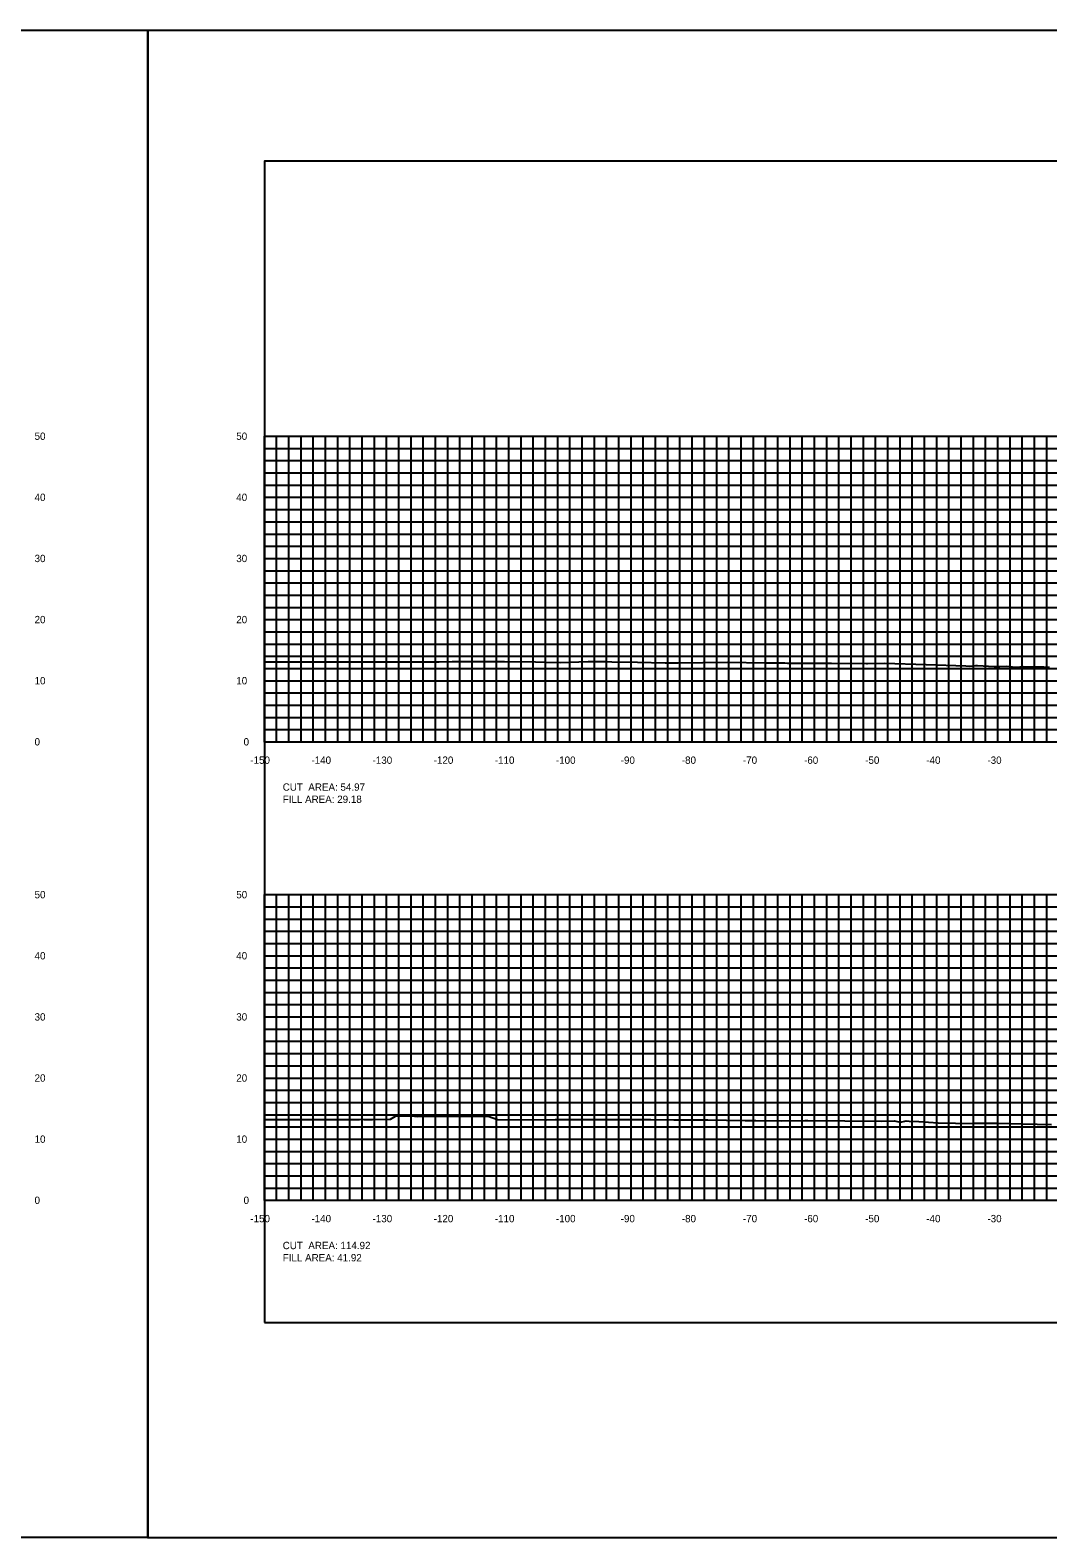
# Model space of a CAD drawing. Extents: x 1797518 to 1804843, y 248068 to 251132.
# Drawn here: x 1804482.7 to 1804649.2, y 250044.2 to 250290.9 of the extents above; entities that cross this region are included whole.
import ezdxf

# ---------------------------------------------------------------- set-up
doc = ezdxf.new("R2010")
doc.units = 0
for name, color, linetype in [('1', 7, 'Continuous'), ('10', 7, 'Continuous'), ('31', 7, 'Continuous'), ('60', 7, 'Continuous'), ('ANNO-TXT', 7, 'Continuous'), ('Level 62', 7, 'Continuous'), ('M-ROADS', 7, 'Continuous')]:
    doc.layers.add(name, color=color, linetype=linetype)

msp = doc.modelspace()

# ---------------------------------------------------------------- linework, layer by layer
msp.add_lwpolyline([(1804521, 250079.43), (1804821, 250079.43), (1804821, 250269.43), (1804521, 250269.43)], close=True)
at = {"layer": '1'}
for points in [[(1804164.33, 250290.86), (1804501.93, 250290.86), (1804501.93, 250044.24), (1804164.33, 250044.24)], [(1804501.93, 250290.86), (1804843.47, 250290.86), (1804843.47, 250044.2), (1804501.93, 250044.2)]]:
    msp.add_lwpolyline(points, close=True, dxfattribs=at)
at = {"layer": '60'}
for p, q in [((1804520.94, 250224.43), (1804521, 250224.43)), ((1804521, 250174.43), (1804521, 250224.43)), ((1804520.94, 250214.43), (1804521, 250214.43)), ((1804520.94, 250204.43), (1804521, 250204.43)), ((1804520.94, 250194.43), (1804521, 250194.43)), ((1804520.94, 250184.43), (1804521, 250184.43)), ((1804520.94, 250174.43), (1804521, 250174.43)), ((1804521, 250174.43), (1804821, 250174.43)), ((1804521, 250174.37), (1804521, 250174.43)), ((1804531, 250174.37), (1804531, 250174.43)), ((1804541, 250174.37), (1804541, 250174.43)), ((1804551, 250174.37), (1804551, 250174.43)), ((1804561, 250174.37), (1804561, 250174.43)), ((1804571, 250174.37), (1804571, 250174.43)), ((1804581, 250174.37), (1804581, 250174.43)), ((1804591, 250174.37), (1804591, 250174.43)), ((1804601, 250174.37), (1804601, 250174.43)), ((1804611, 250174.37), (1804611, 250174.43)), ((1804621, 250174.37), (1804621, 250174.43)), ((1804631, 250174.37), (1804631, 250174.43)), ((1804641, 250174.37), (1804641, 250174.43)), ((1804520.94, 250149.43), (1804521, 250149.43)), ((1804521, 250099.43), (1804521, 250149.43)), ((1804520.94, 250139.43), (1804521, 250139.43)), ((1804520.94, 250129.43), (1804521, 250129.43)), ((1804520.94, 250119.43), (1804521, 250119.43)), ((1804520.94, 250109.43), (1804521, 250109.43)), ((1804520.94, 250099.43), (1804521, 250099.43)), ((1804521, 250099.43), (1804821, 250099.43)), ((1804521, 250099.37), (1804521, 250099.43)), ((1804531, 250099.37), (1804531, 250099.43)), ((1804541, 250099.37), (1804541, 250099.43)), ((1804551, 250099.37), (1804551, 250099.43)), ((1804561, 250099.37), (1804561, 250099.43)), ((1804571, 250099.37), (1804571, 250099.43)), ((1804581, 250099.37), (1804581, 250099.43)), ((1804591, 250099.37), (1804591, 250099.43)), ((1804601, 250099.37), (1804601, 250099.43)), ((1804611, 250099.37), (1804611, 250099.43)), ((1804621, 250099.37), (1804621, 250099.43)), ((1804631, 250099.37), (1804631, 250099.43)), ((1804641, 250099.37), (1804641, 250099.43))]:
    msp.add_line(p, q, dxfattribs=at)
at = {"layer": 'Level 62'}
for p, q in [((1804521, 250224.43), (1804821, 250224.43)), ((1804521, 250174.43), (1804521, 250224.43)), ((1804523, 250174.43), (1804523, 250224.43)), ((1804525, 250174.43), (1804525, 250224.43)), ((1804527, 250174.43), (1804527, 250224.43)), ((1804529, 250174.43), (1804529, 250224.43)), ((1804531, 250174.43), (1804531, 250224.43)), ((1804533, 250174.43), (1804533, 250224.43)), ((1804535, 250174.43), (1804535, 250224.43)), ((1804537, 250174.43), (1804537, 250224.43)), ((1804539, 250174.43), (1804539, 250224.43)), ((1804541, 250174.43), (1804541, 250224.43)), ((1804543, 250174.43), (1804543, 250224.43)), ((1804545, 250174.43), (1804545, 250224.43)), ((1804547, 250174.43), (1804547, 250224.43)), ((1804549, 250174.43), (1804549, 250224.43)), ((1804551, 250174.43), (1804551, 250224.43)), ((1804553, 250174.43), (1804553, 250224.43)), ((1804555, 250174.43), (1804555, 250224.43)), ((1804557, 250174.43), (1804557, 250224.43)), ((1804559, 250174.43), (1804559, 250224.43)), ((1804561, 250174.43), (1804561, 250224.43)), ((1804563, 250174.43), (1804563, 250224.43)), ((1804565, 250174.43), (1804565, 250224.43)), ((1804567, 250174.43), (1804567, 250224.43)), ((1804569, 250174.43), (1804569, 250224.43)), ((1804571, 250174.43), (1804571, 250224.43)), ((1804573, 250174.43), (1804573, 250224.43)), ((1804575, 250174.43), (1804575, 250224.43)), ((1804577, 250174.43), (1804577, 250224.43)), ((1804579, 250174.43), (1804579, 250224.43)), ((1804581, 250174.43), (1804581, 250224.43)), ((1804583, 250174.43), (1804583, 250224.43)), ((1804585, 250174.43), (1804585, 250224.43)), ((1804587, 250174.43), (1804587, 250224.43)), ((1804589, 250174.43), (1804589, 250224.43)), ((1804591, 250174.43), (1804591, 250224.43)), ((1804593, 250174.43), (1804593, 250224.43)), ((1804595, 250174.43), (1804595, 250224.43)), ((1804597, 250174.43), (1804597, 250224.43)), ((1804599, 250174.43), (1804599, 250224.43)), ((1804601, 250174.43), (1804601, 250224.43)), ((1804603, 250174.43), (1804603, 250224.43)), ((1804605, 250174.43), (1804605, 250224.43)), ((1804607, 250174.43), (1804607, 250224.43)), ((1804609, 250174.43), (1804609, 250224.43)), ((1804611, 250174.43), (1804611, 250224.43)), ((1804613, 250174.43), (1804613, 250224.43)), ((1804615, 250174.43), (1804615, 250224.43)), ((1804617, 250174.43), (1804617, 250224.43)), ((1804619, 250174.43), (1804619, 250224.43)), ((1804621, 250174.43), (1804621, 250224.43)), ((1804623, 250174.43), (1804623, 250224.43)), ((1804625, 250174.43), (1804625, 250224.43)), ((1804627, 250174.43), (1804627, 250224.43)), ((1804629, 250174.43), (1804629, 250224.43)), ((1804631, 250174.43), (1804631, 250224.43)), ((1804633, 250174.43), (1804633, 250224.43)), ((1804635, 250174.43), (1804635, 250224.43)), ((1804637, 250174.43), (1804637, 250224.43)), ((1804639, 250174.43), (1804639, 250224.43)), ((1804641, 250174.43), (1804641, 250224.43)), ((1804643, 250174.43), (1804643, 250224.43)), ((1804645, 250174.43), (1804645, 250224.43)), ((1804647, 250174.43), (1804647, 250224.43)), ((1804649, 250174.43), (1804649, 250224.43)), ((1804521, 250222.43), (1804821, 250222.43)), ((1804521, 250220.43), (1804821, 250220.43)), ((1804521, 250218.43), (1804821, 250218.43)), ((1804521, 250216.43), (1804821, 250216.43)), ((1804521, 250214.43), (1804821, 250214.43)), ((1804521, 250212.43), (1804821, 250212.43)), ((1804521, 250210.43), (1804821, 250210.43)), ((1804521, 250208.43), (1804821, 250208.43)), ((1804521, 250206.43), (1804821, 250206.43)), ((1804521, 250204.43), (1804821, 250204.43)), ((1804521, 250202.43), (1804821, 250202.43)), ((1804521, 250200.43), (1804821, 250200.43)), ((1804521, 250198.43), (1804821, 250198.43)), ((1804521, 250196.43), (1804821, 250196.43)), ((1804521, 250194.43), (1804821, 250194.43)), ((1804521, 250192.43), (1804821, 250192.43)), ((1804521, 250190.43), (1804821, 250190.43)), ((1804521, 250188.43), (1804821, 250188.43)), ((1804521, 250186.43), (1804821, 250186.43)), ((1804521, 250184.43), (1804821, 250184.43)), ((1804521, 250182.43), (1804821, 250182.43)), ((1804521, 250180.43), (1804821, 250180.43)), ((1804521, 250178.43), (1804821, 250178.43)), ((1804521, 250176.43), (1804821, 250176.43)), ((1804521, 250174.43), (1804821, 250174.43)), ((1804521, 250149.43), (1804821, 250149.43)), ((1804521, 250099.43), (1804521, 250149.43)), ((1804523, 250099.43), (1804523, 250149.43)), ((1804525, 250099.43), (1804525, 250149.43)), ((1804527, 250099.43), (1804527, 250149.43)), ((1804529, 250099.43), (1804529, 250149.43)), ((1804531, 250099.43), (1804531, 250149.43)), ((1804533, 250099.43), (1804533, 250149.43)), ((1804535, 250099.43), (1804535, 250149.43)), ((1804537, 250099.43), (1804537, 250149.43)), ((1804539, 250099.43), (1804539, 250149.43)), ((1804541, 250099.43), (1804541, 250149.43)), ((1804543, 250099.43), (1804543, 250149.43)), ((1804545, 250099.43), (1804545, 250149.43)), ((1804547, 250099.43), (1804547, 250149.43)), ((1804549, 250099.43), (1804549, 250149.43)), ((1804551, 250099.43), (1804551, 250149.43)), ((1804553, 250099.43), (1804553, 250149.43)), ((1804555, 250099.43), (1804555, 250149.43)), ((1804557, 250099.43), (1804557, 250149.43)), ((1804559, 250099.43), (1804559, 250149.43)), ((1804561, 250099.43), (1804561, 250149.43)), ((1804563, 250099.43), (1804563, 250149.43)), ((1804565, 250099.43), (1804565, 250149.43)), ((1804567, 250099.43), (1804567, 250149.43)), ((1804569, 250099.43), (1804569, 250149.43)), ((1804571, 250099.43), (1804571, 250149.43)), ((1804573, 250099.43), (1804573, 250149.43)), ((1804575, 250099.43), (1804575, 250149.43)), ((1804577, 250099.43), (1804577, 250149.43)), ((1804579, 250099.43), (1804579, 250149.43)), ((1804581, 250099.43), (1804581, 250149.43)), ((1804583, 250099.43), (1804583, 250149.43)), ((1804585, 250099.43), (1804585, 250149.43)), ((1804587, 250099.43), (1804587, 250149.43)), ((1804589, 250099.43), (1804589, 250149.43)), ((1804591, 250099.43), (1804591, 250149.43)), ((1804593, 250099.43), (1804593, 250149.43)), ((1804595, 250099.43), (1804595, 250149.43)), ((1804597, 250099.43), (1804597, 250149.43)), ((1804599, 250099.43), (1804599, 250149.43)), ((1804601, 250099.43), (1804601, 250149.43)), ((1804603, 250099.43), (1804603, 250149.43)), ((1804605, 250099.43), (1804605, 250149.43)), ((1804607, 250099.43), (1804607, 250149.43)), ((1804609, 250099.43), (1804609, 250149.43)), ((1804611, 250099.43), (1804611, 250149.43)), ((1804613, 250099.43), (1804613, 250149.43)), ((1804615, 250099.43), (1804615, 250149.43)), ((1804617, 250099.43), (1804617, 250149.43)), ((1804619, 250099.43), (1804619, 250149.43)), ((1804621, 250099.43), (1804621, 250149.43)), ((1804623, 250099.43), (1804623, 250149.43)), ((1804625, 250099.43), (1804625, 250149.43)), ((1804627, 250099.43), (1804627, 250149.43)), ((1804629, 250099.43), (1804629, 250149.43)), ((1804631, 250099.43), (1804631, 250149.43)), ((1804633, 250099.43), (1804633, 250149.43)), ((1804635, 250099.43), (1804635, 250149.43)), ((1804637, 250099.43), (1804637, 250149.43)), ((1804639, 250099.43), (1804639, 250149.43)), ((1804641, 250099.43), (1804641, 250149.43)), ((1804643, 250099.43), (1804643, 250149.43)), ((1804645, 250099.43), (1804645, 250149.43)), ((1804647, 250099.43), (1804647, 250149.43)), ((1804649, 250099.43), (1804649, 250149.43)), ((1804521, 250147.43), (1804821, 250147.43)), ((1804521, 250145.43), (1804821, 250145.43)), ((1804521, 250143.43), (1804821, 250143.43)), ((1804521, 250141.43), (1804821, 250141.43)), ((1804521, 250139.43), (1804821, 250139.43)), ((1804521, 250137.43), (1804821, 250137.43)), ((1804521, 250135.43), (1804821, 250135.43)), ((1804521, 250133.43), (1804821, 250133.43)), ((1804521, 250131.43), (1804821, 250131.43)), ((1804521, 250129.43), (1804821, 250129.43)), ((1804521, 250127.43), (1804821, 250127.43)), ((1804521, 250125.43), (1804821, 250125.43)), ((1804521, 250123.43), (1804821, 250123.43)), ((1804521, 250121.43), (1804821, 250121.43)), ((1804521, 250119.43), (1804821, 250119.43)), ((1804521, 250117.43), (1804821, 250117.43)), ((1804521, 250115.43), (1804821, 250115.43)), ((1804521, 250113.43), (1804821, 250113.43)), ((1804521, 250111.43), (1804821, 250111.43)), ((1804521, 250109.43), (1804821, 250109.43)), ((1804521, 250107.43), (1804821, 250107.43)), ((1804521, 250105.43), (1804821, 250105.43)), ((1804521, 250103.43), (1804821, 250103.43)), ((1804521, 250101.43), (1804821, 250101.43)), ((1804521, 250099.43), (1804821, 250099.43))]:
    msp.add_line(p, q, dxfattribs=at)
at = {"layer": 'M-ROADS'}
for points in [[(1804521, 250187.52), (1804521.07, 250187.52), (1804525.7, 250187.52), (1804527.33, 250187.5), (1804529.39, 250187.51), (1804530.58, 250187.5), (1804530.98, 250187.53), (1804531.26, 250187.51), (1804532.33, 250187.53), (1804532.71, 250187.53), (1804533.65, 250187.54), (1804537.68, 250187.53), (1804540.91, 250187.54), (1804540.97, 250187.54), (1804541.01, 250187.54), (1804549.58, 250187.51), (1804551.71, 250187.55), (1804553.12, 250187.56), (1804555.8, 250187.57), (1804557.08, 250187.58), (1804559.23, 250187.59), (1804559.37, 250187.58), (1804559.7, 250187.59), (1804559.83, 250187.59), (1804560.3, 250187.58), (1804565.38, 250187.51), (1804566.9, 250187.48), (1804569.43, 250187.39), (1804569.47, 250187.39), (1804573.95, 250187.57), (1804576.78, 250187.56), (1804578.96, 250187.48), (1804581.06, 250187.49), (1804582.07, 250187.47), (1804586.59, 250187.38), (1804588.68, 250187.33), (1804596.78, 250187.45), (1804602.93, 250187.34), (1804605.74, 250187.34), (1804606.14, 250187.33), (1804606.58, 250187.31), (1804609.81, 250187.31), (1804613.81, 250187.29), (1804619.53, 250187.26), (1804619.6, 250187.26), (1804619.66, 250187.26), (1804622.46, 250187.3), (1804629.28, 250187.07), (1804635.74, 250186.85), (1804636.29, 250186.83), (1804637.37, 250186.93), (1804637.53, 250186.9), (1804637.67, 250186.94), (1804640.4, 250186.78), (1804640.72, 250186.74), (1804641.34, 250186.74), (1804642.35, 250186.79), (1804643.92, 250186.63), (1804643.93, 250186.63), (1804645.2, 250186.78), (1804648.52, 250186.71), (1804649.46, 250186.62)], [(1804521, 250112.65), (1804528.19, 250112.64), (1804531.51, 250112.66), (1804534.47, 250112.66), (1804535.76, 250112.65), (1804536.58, 250112.63), (1804537.05, 250112.67), (1804537.26, 250112.65), (1804538.69, 250112.66), (1804541.64, 250112.67), (1804542.48, 250113.17), (1804544.99, 250113.24), (1804546.07, 250113.15), (1804556.04, 250113.19), (1804557.62, 250113.16), (1804559.12, 250112.62), (1804567.2, 250112.6), (1804568.58, 250112.62), (1804569.49, 250112.63), (1804571.23, 250112.64), (1804572.05, 250112.64), (1804573.65, 250112.65), (1804575.19, 250112.65), (1804576.21, 250112.66), (1804578.28, 250112.66), (1804580.09, 250112.65), (1804581.05, 250112.65), (1804581.59, 250112.64), (1804584.25, 250112.63), (1804588.01, 250112.61), (1804591.32, 250112.58), (1804592.3, 250112.57), (1804593.05, 250112.57), (1804593.55, 250112.57), (1804599.65, 250112.5), (1804601.43, 250112.47), (1804605.57, 250112.42), (1804609.45, 250112.48), (1804609.85, 250112.47), (1804609.9, 250112.47), (1804622, 250112.39), (1804624.04, 250112.4), (1804625.09, 250112.19), (1804625.98, 250112.4), (1804626.47, 250112.39), (1804628.06, 250112.29), (1804631.26, 250112.08), (1804636.92, 250112), (1804637.16, 250112.03), (1804638.44, 250112.03), (1804640.14, 250112.03), (1804641.13, 250112.02), (1804645.07, 250111.93), (1804649.78, 250111.81)]]:
    msp.add_lwpolyline(points, dxfattribs=at)

# ---------------------------------------------------------------- texts
at = {"layer": '10'}
for s, p in [('-150', (1804518.7, 250170.83)), ('-140', (1804528.7, 250170.83)), ('-130', (1804538.7, 250170.83)), ('-120', (1804548.7, 250170.83)), ('-110', (1804558.7, 250170.83)), ('-100', (1804568.7, 250170.83)), ('-90', (1804579.3, 250170.83)), ('-80', (1804589.3, 250170.83)), ('-70', (1804599.3, 250170.83)), ('-60', (1804609.3, 250170.83)), ('-50', (1804619.3, 250170.83)), ('-40', (1804629.3, 250170.83)), ('-30', (1804639.3, 250170.83)), ('-150', (1804518.7, 250095.83)), ('-140', (1804528.7, 250095.83)), ('-130', (1804538.7, 250095.83)), ('-120', (1804548.7, 250095.83)), ('-110', (1804558.7, 250095.83)), ('-100', (1804568.7, 250095.83)), ('-90', (1804579.3, 250095.83)), ('-80', (1804589.3, 250095.83)), ('-70', (1804599.3, 250095.83)), ('-60', (1804609.3, 250095.83)), ('-50', (1804619.3, 250095.83)), ('-40', (1804629.3, 250095.83)), ('-30', (1804639.3, 250095.83))]:
    msp.add_text(s, height=1.2, dxfattribs=at).set_placement(p)
at = {"layer": '31'}
for s, p in [('50', (1804483.4, 250223.83)), ('50', (1804516.4, 250223.83)), ('40', (1804483.4, 250213.83)), ('40', (1804516.4, 250213.83)), ('30', (1804483.4, 250203.83)), ('30', (1804516.4, 250203.83)), ('20', (1804483.4, 250193.83)), ('20', (1804516.4, 250193.83)), ('10', (1804483.4, 250183.83)), ('10', (1804516.4, 250183.83)), ('0', (1804483.4, 250173.83)), ('0', (1804517.6, 250173.83)), ('50', (1804483.4, 250148.83)), ('50', (1804516.4, 250148.83)), ('40', (1804483.4, 250138.83)), ('40', (1804516.4, 250138.83)), ('30', (1804483.4, 250128.83)), ('30', (1804516.4, 250128.83)), ('20', (1804483.4, 250118.83)), ('20', (1804516.4, 250118.83)), ('10', (1804483.4, 250108.83)), ('10', (1804516.4, 250108.83)), ('0', (1804483.4, 250098.83)), ('0', (1804517.6, 250098.83))]:
    msp.add_text(s, height=1.2, dxfattribs=at).set_placement(p)
at = {"layer": '60'}
for p in [(1804521, 250174.43), (1804521, 250099.43)]:
    msp.add_text('-', height=0.0001, dxfattribs=at).set_placement(p)
at = {"layer": 'ANNO-TXT'}
for s, p in [('CUT  AREA: 54.97', (1804524, 250166.43)), ('FILL AREA: 29.18', (1804524, 250164.43)), ('CUT  AREA: 114.92', (1804524, 250091.43)), ('FILL AREA: 41.92', (1804524, 250089.43))]:
    msp.add_text(s, height=1.2, dxfattribs=at).set_placement(p)

doc.saveas('drawing.dxf')
